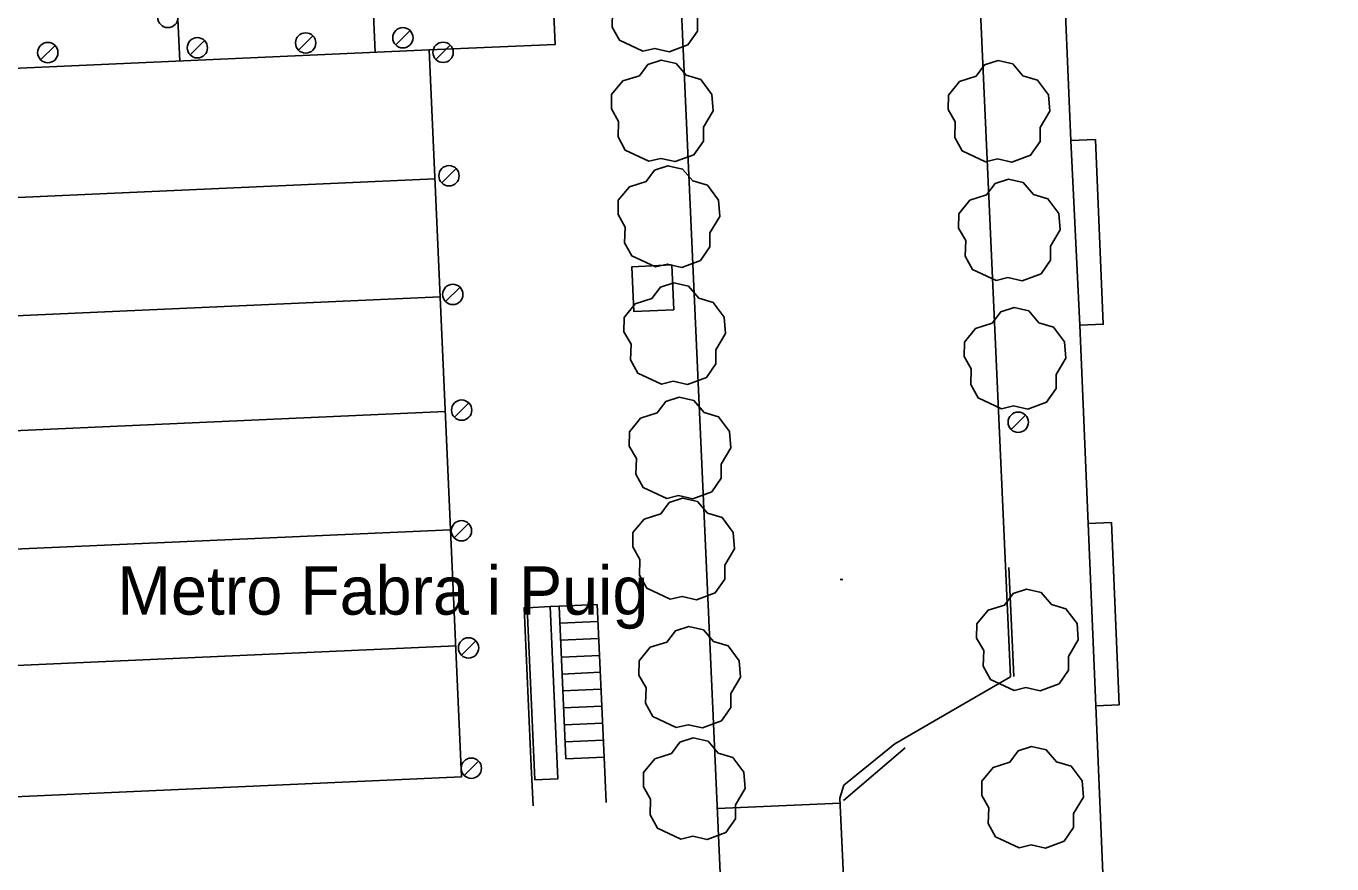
# Model space of a CAD drawing. Extents: x 431390 to 432653, y 4586754 to 4589600.
# Drawn here: x 431745 to 431796.4, y 4586905.4 to 4586938.4 of the extents above; entities that cross this region are included whole.
import ezdxf

# ---------------------------------------------------------------- set-up
doc = ezdxf.new("R2010")
doc.units = 0
for name, color, linetype in [('COM_17LS_LN', 7, 'Continuous'), ('COM_51_LN', 7, 'Continuous'), ('CON_01_LN', 7, 'Continuous'), ('CON_01FI_LN', 7, 'Continuous'), ('CON_04_LN', 7, 'Continuous'), ('CON_07_LN', 7, 'Continuous'), ('CON_14LS_LN', 7, 'Continuous'), ('CON_15_LN', 7, 'Continuous'), ('CON_17_LN', 7, 'Continuous'), ('CON_20_LN', 7, 'Continuous'), ('CON_23_LN', 7, 'Continuous'), ('CON_29_LN', 7, 'Continuous'), ('CON_34_LN', 7, 'Continuous'), ('ENE_06_PT', 7, 'Continuous'), ('ORO_03_PT', 7, 'Continuous'), ('TOP_17_TX', 7, 'Continuous'), ('VEG_03_PT', 7, 'Continuous')]:
    doc.layers.add(name, color=color, linetype=linetype)

msp = doc.modelspace()

# ---------------------------------------------------------------- linework, layer by layer
at = {"layer": 'COM_17LS_LN'}
for points in [[(431796.36, 4586843.5), (431784.88, 4586843.889), (431784.266, 4586843.982), (431783.664, 4586844.138), (431783.082, 4586844.355), (431782.526, 4586844.631), (431782.001, 4586844.962), (431781.512, 4586845.346), (431781.066, 4586845.778), (431780.667, 4586846.254), (431780.319, 4586846.768), (431780.025, 4586847.315), (431779.79, 4586847.89), (431777, 4586908.02), (431777.16, 4586908.53), (431779.16, 4586910.16), (431781.124, 4586911.301), (431783.707, 4586912.802), (431781.939, 4586952.061), (431780.022, 4586994.644), (431779.988, 4586995.394)], [(431770.201, 4586951.533), (431772.015, 4586911.246), (431772.306, 4586904.782)]]:
    msp.add_lwpolyline(points, dxfattribs=at)
at = {"layer": 'COM_51_LN'}
msp.add_lwpolyline([(431772.178, 4586907.616), (431777.009, 4586907.833)], dxfattribs=at)
at = {"layer": 'CON_01_LN'}
for points in [[(431785.763, 4586941.72), (431786.09, 4586933.903)], [(431732.105, 4586936.188), (431760.833, 4586937.472), (431762.112, 4586908.865), (431733.384, 4586907.58), (431732.105, 4586936.188)], [(431786.447, 4586926.638), (431786.774, 4586918.835)], [(431787.067, 4586911.66), (431787.396, 4586903.811)]]:
    msp.add_lwpolyline(points, dxfattribs=at)
at = {"layer": 'CON_01FI_LN'}
for points in [[(431786.09, 4586933.903), (431787.061, 4586933.944), (431787.365, 4586926.676), (431786.447, 4586926.638)], [(431786.774, 4586918.835), (431787.693, 4586918.873), (431787.993, 4586911.699), (431787.067, 4586911.66)]]:
    msp.add_lwpolyline(points, dxfattribs=at)
at = {"layer": 'CON_04_LN'}
for points in [[(431761.267, 4586927.758), (431732.539, 4586926.474)], [(431732.949, 4586917.306), (431761.677, 4586918.591)]]:
    msp.add_lwpolyline(points, dxfattribs=at)
at = {"layer": 'CON_07_LN'}
for points in [[(431758.718, 4586937.377), (431758.57, 4586940.685), (431750.875, 4586940.341), (431751.023, 4586937.034)], [(431770.471, 4586927.244), (431768.893, 4586927.173), (431768.814, 4586928.938), (431770.392, 4586929.009), (431770.471, 4586927.244)]]:
    msp.add_lwpolyline(points, dxfattribs=at)
at = {"layer": 'CON_14LS_LN'}
for points in [[(431764.856, 4586909.27), (431764.575, 4586915.516), (431764.696, 4586915.521)], [(431765.949, 4586915.577), (431765.595, 4586915.562)]]:
    msp.add_lwpolyline(points, dxfattribs=at)
at = {"layer": 'CON_15_LN'}
for points in [[(431786.09, 4586933.903), (431786.447, 4586926.638)], [(431786.774, 4586918.835), (431787.067, 4586911.66)]]:
    msp.add_lwpolyline(points, dxfattribs=at)
at = {"layer": 'CON_17_LN'}
msp.add_lwpolyline([(431753.698, 4587017.012), (431762.84, 4587006.53), (431763.211, 4586998.291), (431763.26, 4586994.054), (431765.185, 4586951.307), (431765.798, 4586937.694), (431760.833, 4586937.472)], dxfattribs=at)
at = {"layer": 'CON_20_LN'}
for points in [[(431783.844, 4586912.808), (431783.651, 4586917.104)], [(431767.718, 4586909.641), (431767.799, 4586907.849)], [(431777.14, 4586907.93), (431779.57, 4586910.01)], [(431764.926, 4586907.72), (431764.856, 4586909.27)]]:
    msp.add_lwpolyline(points, dxfattribs=at)
at = {"layer": 'CON_23_LN'}
for points in [[(431765.949, 4586915.577), (431767.447, 4586915.645), (431767.718, 4586909.641)], [(431765.949, 4586915.577), (431766.22, 4586909.573)], [(431767.477, 4586914.978), (431765.979, 4586914.91)], [(431767.507, 4586914.311), (431766.009, 4586914.243)], [(431767.537, 4586913.644), (431766.039, 4586913.576)], [(431767.567, 4586912.977), (431766.069, 4586912.909)], [(431767.598, 4586912.309), (431766.1, 4586912.242)], [(431767.628, 4586911.642), (431766.13, 4586911.575)], [(431767.658, 4586910.975), (431766.16, 4586910.908)], [(431767.688, 4586910.308), (431766.19, 4586910.24)], [(431767.718, 4586909.641), (431766.22, 4586909.573)]]:
    msp.add_lwpolyline(points, dxfattribs=at)
at = {"layer": 'CON_29_LN'}
for points in [[(431761.06, 4586932.401), (431732.332, 4586931.117)], [(431761.469, 4586923.237), (431732.741, 4586921.953)], [(431761.881, 4586914.021), (431733.153, 4586912.736)]]:
    msp.add_lwpolyline(points, dxfattribs=at)
at = {"layer": 'CON_34_LN'}
msp.add_lwpolyline([(431764.696, 4586915.521), (431765.001, 4586908.739), (431765.9, 4586908.779), (431765.595, 4586915.562), (431764.696, 4586915.521)], dxfattribs=at)
at = {"layer": 'ENE_06_PT'}
for p, q in [((431756.262, 4586938.031), (431755.696, 4586937.465)), ((431760.086, 4586938.237), (431759.52, 4586937.671)), ((431746.115, 4586937.651), (431745.549, 4586937.085)), ((431752, 4586937.843), (431751.434, 4586937.277)), ((431761.668, 4586937.662), (431761.102, 4586937.096)), ((431761.902, 4586932.805), (431761.336, 4586932.239)), ((431762.052, 4586928.134), (431761.486, 4586927.568)), ((431762.399, 4586923.58), (431761.833, 4586923.014)), ((431784.302, 4586923.102), (431783.736, 4586922.536)), ((431762.391, 4586918.832), (431761.825, 4586918.266)), ((431762.671, 4586914.219), (431762.105, 4586913.653)), ((431762.781, 4586909.485), (431762.215, 4586908.919))]:
    msp.add_line(p, q, dxfattribs=at)
for centre in [(431750.559, 4586938.752), (431751.717, 4586937.56), (431755.979, 4586937.748), (431759.803, 4586937.954), (431745.832, 4586937.368), (431761.385, 4586937.379), (431761.619, 4586932.522), (431761.769, 4586927.851), (431762.116, 4586923.297), (431784.019, 4586922.819), (431762.108, 4586918.549), (431762.388, 4586913.936), (431762.498, 4586909.202)]:
    msp.add_circle(centre, 0.4, dxfattribs=at)
at = {"layer": 'ORO_03_PT'}
msp.add_line((431777.012, 4586916.624), (431777.112, 4586916.624), dxfattribs=at)
at = {"layer": 'VEG_03_PT'}
for points in [[(431769.25, 4586937.42), (431768.323, 4586937.855), (431768.035, 4586938.376), (431768.058, 4586938.99), (431767.776, 4586939.482), (431767.784, 4586940.045), (431768.225, 4586940.58), (431768.878, 4586940.784), (431769.213, 4586941.235), (431769.739, 4586941.405), (431770.319, 4586941.272), (431770.719, 4586940.806), (431771.293, 4586940.636), (431771.727, 4586940.053), (431771.776, 4586939.411), (431771.393, 4586938.764), (431771.393, 4586938.214), (431771.021, 4586937.68), (431770.282, 4586937.405), (431769.717, 4586937.533), (431769.25, 4586937.42)], [(431769.484, 4586933.091), (431768.557, 4586933.526), (431768.269, 4586934.047), (431768.292, 4586934.661), (431768.01, 4586935.153), (431768.018, 4586935.716), (431768.459, 4586936.251), (431769.112, 4586936.455), (431769.447, 4586936.906), (431769.973, 4586937.076), (431770.553, 4586936.943), (431770.953, 4586936.477), (431771.527, 4586936.307), (431771.961, 4586935.724), (431772.01, 4586935.082), (431771.627, 4586934.435), (431771.627, 4586933.885), (431771.255, 4586933.351), (431770.516, 4586933.076), (431769.951, 4586933.204), (431769.484, 4586933.091)], [(431782.734, 4586933.071), (431781.807, 4586933.506), (431781.519, 4586934.027), (431781.542, 4586934.641), (431781.26, 4586935.133), (431781.268, 4586935.696), (431781.709, 4586936.231), (431782.362, 4586936.435), (431782.697, 4586936.886), (431783.223, 4586937.056), (431783.803, 4586936.923), (431784.203, 4586936.457), (431784.777, 4586936.287), (431785.211, 4586935.704), (431785.26, 4586935.062), (431784.877, 4586934.415), (431784.877, 4586933.865), (431784.505, 4586933.331), (431783.766, 4586933.056), (431783.201, 4586933.184), (431782.734, 4586933.071)], [(431769.744, 4586928.931), (431768.817, 4586929.366), (431768.529, 4586929.887), (431768.552, 4586930.501), (431768.27, 4586930.993), (431768.278, 4586931.556), (431768.719, 4586932.091), (431769.372, 4586932.295), (431769.707, 4586932.746), (431770.233, 4586932.916), (431770.813, 4586932.783), (431771.213, 4586932.317), (431771.787, 4586932.147), (431772.221, 4586931.564), (431772.27, 4586930.922), (431771.887, 4586930.275), (431771.887, 4586929.725), (431771.515, 4586929.191), (431770.776, 4586928.916), (431770.211, 4586929.044), (431769.744, 4586928.931)], [(431783.144, 4586928.401), (431782.217, 4586928.836), (431781.929, 4586929.357), (431781.952, 4586929.971), (431781.67, 4586930.463), (431781.678, 4586931.026), (431782.119, 4586931.561), (431782.772, 4586931.765), (431783.107, 4586932.216), (431783.633, 4586932.386), (431784.213, 4586932.253), (431784.613, 4586931.787), (431785.187, 4586931.617), (431785.621, 4586931.034), (431785.67, 4586930.392), (431785.287, 4586929.745), (431785.287, 4586929.195), (431784.915, 4586928.661), (431784.176, 4586928.386), (431783.611, 4586928.514), (431783.144, 4586928.401)], [(431769.974, 4586924.321), (431769.047, 4586924.756), (431768.759, 4586925.277), (431768.782, 4586925.891), (431768.5, 4586926.383), (431768.508, 4586926.946), (431768.949, 4586927.481), (431769.602, 4586927.685), (431769.937, 4586928.136), (431770.463, 4586928.306), (431771.043, 4586928.173), (431771.443, 4586927.707), (431772.017, 4586927.537), (431772.451, 4586926.954), (431772.5, 4586926.312), (431772.117, 4586925.665), (431772.117, 4586925.115), (431771.745, 4586924.581), (431771.006, 4586924.306), (431770.441, 4586924.434), (431769.974, 4586924.321)], [(431783.364, 4586923.351), (431782.437, 4586923.786), (431782.149, 4586924.307), (431782.172, 4586924.921), (431781.89, 4586925.413), (431781.898, 4586925.976), (431782.339, 4586926.511), (431782.992, 4586926.715), (431783.327, 4586927.166), (431783.853, 4586927.336), (431784.433, 4586927.203), (431784.833, 4586926.737), (431785.407, 4586926.567), (431785.841, 4586925.984), (431785.89, 4586925.342), (431785.507, 4586924.695), (431785.507, 4586924.145), (431785.135, 4586923.611), (431784.396, 4586923.336), (431783.831, 4586923.464), (431783.364, 4586923.351)], [(431770.184, 4586919.821), (431769.257, 4586920.256), (431768.969, 4586920.777), (431768.992, 4586921.391), (431768.71, 4586921.883), (431768.718, 4586922.446), (431769.159, 4586922.981), (431769.812, 4586923.185), (431770.147, 4586923.636), (431770.673, 4586923.806), (431771.253, 4586923.673), (431771.653, 4586923.207), (431772.227, 4586923.037), (431772.661, 4586922.454), (431772.71, 4586921.812), (431772.327, 4586921.165), (431772.327, 4586920.615), (431771.955, 4586920.081), (431771.216, 4586919.806), (431770.651, 4586919.934), (431770.184, 4586919.821)], [(431770.324, 4586915.851), (431769.397, 4586916.286), (431769.109, 4586916.807), (431769.132, 4586917.421), (431768.85, 4586917.913), (431768.858, 4586918.476), (431769.299, 4586919.011), (431769.952, 4586919.215), (431770.287, 4586919.666), (431770.813, 4586919.836), (431771.393, 4586919.703), (431771.793, 4586919.237), (431772.367, 4586919.067), (431772.801, 4586918.484), (431772.85, 4586917.842), (431772.467, 4586917.195), (431772.467, 4586916.645), (431772.095, 4586916.111), (431771.356, 4586915.836), (431770.791, 4586915.964), (431770.324, 4586915.851)], [(431783.854, 4586912.261), (431782.927, 4586912.696), (431782.639, 4586913.217), (431782.662, 4586913.831), (431782.38, 4586914.323), (431782.388, 4586914.886), (431782.829, 4586915.421), (431783.482, 4586915.625), (431783.817, 4586916.076), (431784.343, 4586916.246), (431784.923, 4586916.113), (431785.323, 4586915.647), (431785.897, 4586915.477), (431786.331, 4586914.894), (431786.38, 4586914.252), (431785.997, 4586913.605), (431785.997, 4586913.055), (431785.625, 4586912.521), (431784.886, 4586912.246), (431784.321, 4586912.374), (431783.854, 4586912.261)], [(431770.564, 4586910.801), (431769.637, 4586911.236), (431769.349, 4586911.757), (431769.372, 4586912.371), (431769.09, 4586912.863), (431769.098, 4586913.426), (431769.539, 4586913.961), (431770.192, 4586914.165), (431770.527, 4586914.616), (431771.053, 4586914.786), (431771.633, 4586914.653), (431772.033, 4586914.187), (431772.607, 4586914.017), (431773.041, 4586913.434), (431773.09, 4586912.792), (431772.707, 4586912.145), (431772.707, 4586911.595), (431772.335, 4586911.061), (431771.596, 4586910.786), (431771.031, 4586910.914), (431770.564, 4586910.801)], [(431770.744, 4586906.411), (431769.817, 4586906.846), (431769.529, 4586907.367), (431769.552, 4586907.981), (431769.27, 4586908.473), (431769.278, 4586909.036), (431769.719, 4586909.571), (431770.372, 4586909.775), (431770.707, 4586910.226), (431771.233, 4586910.396), (431771.813, 4586910.263), (431772.213, 4586909.797), (431772.787, 4586909.627), (431773.221, 4586909.044), (431773.27, 4586908.402), (431772.887, 4586907.755), (431772.887, 4586907.205), (431772.515, 4586906.671), (431771.776, 4586906.396), (431771.211, 4586906.524), (431770.744, 4586906.411)], [(431784.054, 4586906.071), (431783.127, 4586906.506), (431782.839, 4586907.027), (431782.862, 4586907.641), (431782.58, 4586908.133), (431782.588, 4586908.696), (431783.029, 4586909.231), (431783.682, 4586909.435), (431784.017, 4586909.886), (431784.543, 4586910.056), (431785.123, 4586909.923), (431785.523, 4586909.457), (431786.097, 4586909.287), (431786.531, 4586908.704), (431786.58, 4586908.062), (431786.197, 4586907.415), (431786.197, 4586906.865), (431785.825, 4586906.331), (431785.086, 4586906.056), (431784.521, 4586906.184), (431784.054, 4586906.071)]]:
    msp.add_lwpolyline(points, dxfattribs=at)

# ---------------------------------------------------------------- texts
at = {"layer": 'TOP_17_TX'}
msp.add_text('Metro Fabra i Puig', height=1.9, dxfattribs=at).set_placement((431748.564, 4586915.246))

doc.saveas('drawing.dxf')
